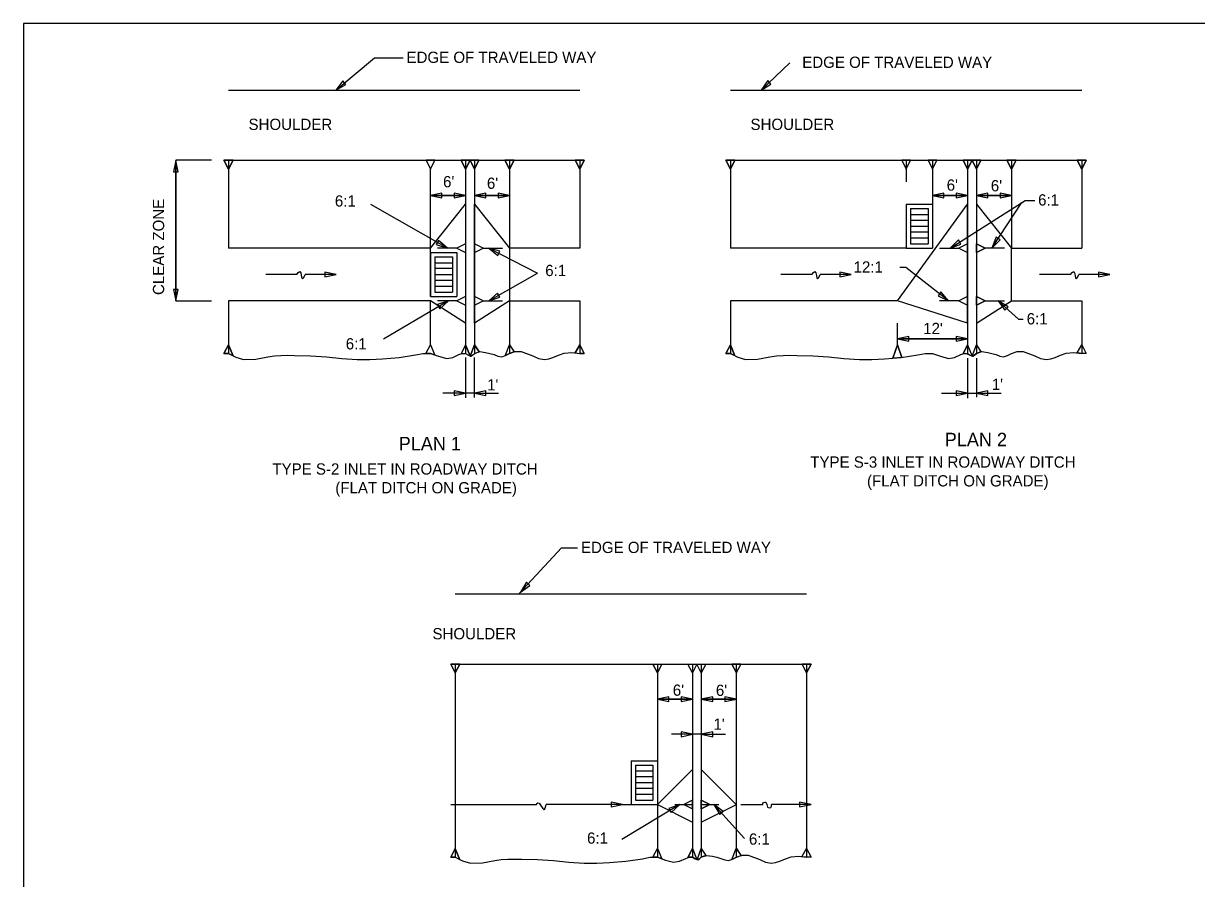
# Model space of a CAD drawing. Extents: x -439.1 to -407.9, y -458.1 to -437.7.
# Drawn here: x -439.11 to -423.48, y -449.07 to -437.68 of the extents above; entities that cross this region are included whole.
import ezdxf

# ---------------------------------------------------------------- set-up
doc = ezdxf.new("R2010")
doc.units = 0
for name, color, linetype in [('Bridge-Named Boundary', 7, 'Continuous'), ('Common-Notes', 7, 'Continuous'), ('Level 4', 7, 'Continuous'), ('Level 45', 7, 'Continuous')]:
    doc.layers.add(name, color=color, linetype=linetype)

msp = doc.modelspace()

# ---------------------------------------------------------------- linework, layer by layer
at = {"layer": 'Bridge-Named Boundary'}
msp.add_lwpolyline([(-439.109, -458.051), (-407.859, -458.051), (-407.859, -437.676), (-439.109, -437.676)], close=True, dxfattribs=at)
at = {"layer": 'Level 4'}
for p, q in [((-434.95, -438.564), (-434.433, -438.133)), ((-434.433, -438.133), (-434.053, -438.133)), ((-429.285, -438.564), (-428.902, -438.202)), ((-436.378, -438.564), (-431.699, -438.564)), ((-429.692, -438.564), (-425.013, -438.564)), ((-436.604, -439.499), (-437.081, -439.499)), ((-437.08, -441.372), (-437.08, -439.5)), ((-437.08, -439.5), (-437.08, -441.372)), ((-436.378, -439.616), (-436.439, -439.499)), ((-436.439, -439.499), (-436.378, -439.499)), ((-436.378, -439.499), (-431.699, -439.499)), ((-436.318, -439.499), (-436.378, -439.616)), ((-436.378, -439.499), (-436.378, -440.67)), ((-433.746, -439.499), (-433.687, -439.616)), ((-433.687, -439.616), (-433.63, -439.499)), ((-433.22, -439.616), (-433.28, -439.499)), ((-433.159, -439.499), (-433.22, -439.616)), ((-433.22, -439.499), (-433.22, -442.073)), ((-433.103, -439.616), (-433.159, -439.499)), ((-433.042, -439.499), (-433.103, -439.616)), ((-433.103, -439.499), (-433.103, -442.073)), ((-432.635, -439.616), (-432.696, -439.499)), ((-432.575, -439.499), (-432.635, -439.616)), ((-432.635, -439.499), (-432.635, -442.073)), ((-431.699, -439.616), (-431.76, -439.499)), ((-431.699, -439.499), (-431.639, -439.499)), ((-431.639, -439.499), (-431.699, -439.616)), ((-431.699, -439.499), (-431.699, -440.67)), ((-429.692, -439.616), (-429.753, -439.499)), ((-429.753, -439.499), (-429.692, -439.499)), ((-429.692, -439.499), (-425.013, -439.499)), ((-429.632, -439.499), (-429.692, -439.616)), ((-429.692, -439.499), (-429.692, -440.67)), ((-427.411, -439.499), (-427.352, -439.616)), ((-427.352, -439.616), (-427.294, -439.499)), ((-427.352, -439.499), (-427.352, -439.785)), ((-427.06, -439.499), (-427.001, -439.616)), ((-427.001, -439.616), (-426.944, -439.499)), ((-427.001, -439.499), (-427.001, -440.67)), ((-426.534, -439.616), (-426.594, -439.499)), ((-426.473, -439.499), (-426.534, -439.616)), ((-426.534, -439.499), (-426.534, -442.073)), ((-426.417, -439.616), (-426.473, -439.499)), ((-426.355, -439.499), (-426.417, -439.616)), ((-426.417, -439.499), (-426.417, -442.073)), ((-425.948, -439.616), (-426.01, -439.499)), ((-425.888, -439.499), (-425.948, -439.616)), ((-425.948, -439.499), (-425.948, -440.67)), ((-425.013, -439.616), (-425.074, -439.499)), ((-425.013, -439.499), (-424.953, -439.499)), ((-424.953, -439.499), (-425.013, -439.616)), ((-425.013, -439.499), (-425.013, -440.67)), ((-433.687, -440.67), (-433.687, -439.616)), ((-433.688, -439.968), (-433.22, -439.968)), ((-433.22, -439.968), (-433.688, -439.968)), ((-433.103, -439.968), (-432.635, -439.968)), ((-432.635, -439.968), (-433.103, -439.968)), ((-427.001, -439.968), (-426.534, -439.968)), ((-426.534, -439.968), (-427.001, -439.968)), ((-426.417, -439.968), (-425.949, -439.968)), ((-425.949, -439.968), (-426.417, -439.968)), ((-433.463, -440.67), (-434.48, -440.09)), ((-433.687, -440.67), (-433.22, -440.085)), ((-433.22, -440.085), (-433.22, -441.671)), ((-433.103, -441.671), (-433.103, -440.085)), ((-433.103, -440.085), (-432.635, -440.67)), ((-427.469, -441.372), (-426.534, -440.085)), ((-427.352, -440.085), (-427.001, -440.085)), ((-427.352, -440.085), (-427.352, -440.67)), ((-427.294, -440.143), (-427.06, -440.143)), ((-427.294, -440.143), (-427.294, -440.612)), ((-427.06, -440.143), (-427.06, -440.612)), ((-427.001, -440.085), (-427.001, -440.67)), ((-426.767, -440.67), (-425.766, -440.033)), ((-426.534, -441.671), (-426.534, -440.085)), ((-426.417, -440.085), (-425.948, -440.67)), ((-426.417, -440.085), (-426.417, -441.671)), ((-426.209, -440.67), (-425.811, -440.061)), ((-425.766, -440.033), (-425.64, -440.033)), ((-427.294, -440.221), (-427.06, -440.221)), ((-427.06, -440.3), (-427.294, -440.3)), ((-427.294, -440.377), (-427.06, -440.377)), ((-427.06, -440.455), (-427.294, -440.455)), ((-433.22, -440.612), (-433.337, -440.67)), ((-432.986, -440.67), (-433.103, -440.612)), ((-427.294, -440.533), (-427.06, -440.533)), ((-427.294, -440.612), (-427.06, -440.612)), ((-426.534, -440.612), (-426.651, -440.67)), ((-426.3, -440.67), (-426.417, -440.612)), ((-433.687, -440.67), (-436.378, -440.67)), ((-433.687, -441.313), (-433.687, -440.67)), ((-433.687, -440.729), (-433.687, -441.313)), ((-433.687, -440.729), (-433.337, -440.729)), ((-433.337, -440.67), (-433.594, -440.67)), ((-433.337, -440.67), (-433.22, -440.729)), ((-433.337, -440.729), (-433.337, -441.313)), ((-433.103, -440.729), (-432.986, -440.67)), ((-432.986, -440.67), (-432.729, -440.67)), ((-432.912, -440.67), (-432.26, -441.003)), ((-432.635, -440.67), (-432.635, -441.372)), ((-431.699, -440.67), (-432.635, -440.67)), ((-427.352, -440.67), (-429.692, -440.67)), ((-427.352, -440.67), (-427.001, -440.67)), ((-426.908, -440.67), (-426.651, -440.67)), ((-426.651, -440.67), (-426.534, -440.729)), ((-426.417, -440.729), (-426.3, -440.67)), ((-426.042, -440.67), (-426.3, -440.67)), ((-425.948, -441.372), (-425.948, -440.67)), ((-425.948, -440.67), (-425.013, -440.67)), ((-433.63, -440.786), (-433.396, -440.786)), ((-433.63, -440.786), (-433.63, -441.255)), ((-433.63, -440.865), (-433.396, -440.865)), ((-433.396, -440.786), (-433.396, -441.255)), ((-427.357, -440.927), (-427.435, -440.927)), ((-426.788, -441.372), (-427.357, -440.927)), ((-435.469, -441.02), (-435.88, -441.02)), ((-434.945, -441.021), (-435.357, -441.021)), ((-433.396, -440.943), (-433.63, -440.943)), ((-433.63, -441.02), (-433.396, -441.02)), ((-432.911, -441.372), (-432.26, -441.003)), ((-428.609, -441.02), (-429.021, -441.02)), ((-428.085, -441.021), (-428.497, -441.021)), ((-425.163, -441.02), (-425.574, -441.02)), ((-424.638, -441.021), (-425.05, -441.021)), ((-433.396, -441.099), (-433.63, -441.099)), ((-433.63, -441.177), (-433.396, -441.177)), ((-437.081, -441.372), (-436.604, -441.372)), ((-436.378, -441.372), (-436.378, -442.073)), ((-433.687, -441.372), (-436.378, -441.372)), ((-433.449, -441.372), (-434.315, -441.883)), ((-433.687, -441.313), (-433.337, -441.313)), ((-433.22, -441.671), (-433.687, -441.372)), ((-433.687, -441.957), (-433.687, -441.372)), ((-433.63, -441.255), (-433.396, -441.255)), ((-433.337, -441.372), (-433.594, -441.372)), ((-433.22, -441.313), (-433.337, -441.372)), ((-433.337, -441.372), (-433.22, -441.43)), ((-432.986, -441.372), (-433.103, -441.313)), ((-432.635, -441.372), (-433.103, -441.671)), ((-433.103, -441.43), (-432.986, -441.372)), ((-432.986, -441.372), (-432.729, -441.372)), ((-432.635, -441.372), (-431.699, -441.372)), ((-431.699, -441.372), (-431.699, -442.073)), ((-429.692, -441.372), (-429.692, -442.073)), ((-427.469, -441.372), (-429.692, -441.372)), ((-426.534, -441.671), (-427.469, -441.372)), ((-426.651, -441.372), (-426.908, -441.372)), ((-426.534, -441.313), (-426.651, -441.372)), ((-426.651, -441.372), (-426.534, -441.43)), ((-426.3, -441.372), (-426.417, -441.313)), ((-426.417, -441.671), (-425.948, -441.372)), ((-426.417, -441.43), (-426.3, -441.372)), ((-426.3, -441.372), (-426.042, -441.372)), ((-426.128, -441.372), (-425.854, -441.618)), ((-425.948, -441.372), (-425.013, -441.372)), ((-425.013, -441.372), (-425.013, -442.073)), ((-427.469, -441.957), (-427.469, -441.671)), ((-425.854, -441.618), (-425.792, -441.618)), ((-436.378, -441.957), (-436.439, -442.073)), ((-436.318, -442.106), (-436.378, -441.957)), ((-433.748, -442.074), (-433.687, -441.957)), ((-433.687, -441.957), (-433.628, -442.094)), ((-433.22, -441.957), (-433.281, -442.078)), ((-433.22, -441.957), (-433.161, -442.106)), ((-433.158, -442.107), (-433.103, -441.957)), ((-433.103, -441.957), (-433.041, -442.052)), ((-432.695, -442.103), (-432.635, -441.957)), ((-432.635, -441.957), (-432.575, -442.051)), ((-431.76, -442.064), (-431.699, -441.957)), ((-431.699, -441.957), (-431.639, -442.073)), ((-429.692, -441.957), (-429.753, -442.073)), ((-429.632, -442.106), (-429.692, -441.957)), ((-427.469, -441.957), (-427.528, -442.135)), ((-427.469, -441.878), (-426.534, -441.878)), ((-426.534, -441.878), (-427.469, -441.878)), ((-427.411, -442.126), (-427.469, -441.957)), ((-426.534, -441.957), (-426.594, -442.076)), ((-426.534, -441.957), (-426.473, -442.109)), ((-426.473, -442.109), (-426.417, -441.957)), ((-426.417, -441.957), (-426.356, -442.05)), ((-425.075, -442.066), (-425.013, -441.957)), ((-425.013, -441.957), (-424.953, -442.073)), ((-436.439, -442.073), (-436.378, -442.073)), ((-433.22, -442.128), (-433.22, -442.666)), ((-433.103, -442.658), (-433.103, -442.128)), ((-431.639, -442.073), (-431.699, -442.073)), ((-429.753, -442.073), (-429.692, -442.073)), ((-426.534, -442.134), (-426.534, -442.669)), ((-426.417, -442.134), (-426.417, -442.656)), ((-424.953, -442.073), (-425.013, -442.073)), ((-433.103, -442.602), (-433.521, -442.602)), ((-433.103, -442.602), (-432.781, -442.602)), ((-426.882, -442.602), (-426.086, -442.602)), ((-432.509, -445.276), (-431.944, -444.663)), ((-431.944, -444.663), (-431.73, -444.663)), ((-433.357, -445.275), (-428.678, -445.275)), ((-433.357, -446.329), (-433.417, -446.212)), ((-433.417, -446.212), (-433.357, -446.212)), ((-433.296, -446.212), (-433.357, -446.329)), ((-433.357, -446.212), (-433.357, -448.784)), ((-433.357, -446.212), (-428.678, -446.212)), ((-430.725, -446.212), (-430.666, -446.329)), ((-430.666, -446.329), (-430.608, -446.212)), ((-430.666, -446.212), (-430.666, -448.785)), ((-430.198, -446.329), (-430.259, -446.212)), ((-430.138, -446.212), (-430.198, -446.329)), ((-430.198, -446.212), (-430.198, -448.784)), ((-430.081, -446.329), (-430.138, -446.212)), ((-430.021, -446.212), (-430.081, -446.329)), ((-430.081, -446.212), (-430.081, -448.784)), ((-429.613, -446.329), (-429.674, -446.212)), ((-429.552, -446.212), (-429.614, -446.329)), ((-429.614, -446.212), (-429.614, -448.784)), ((-428.678, -446.329), (-428.738, -446.212)), ((-428.678, -446.212), (-428.617, -446.212)), ((-428.617, -446.212), (-428.678, -446.329)), ((-428.678, -446.212), (-428.678, -448.784)), ((-430.666, -446.679), (-430.198, -446.679)), ((-430.198, -446.679), (-430.666, -446.679)), ((-430.081, -446.679), (-429.613, -446.679)), ((-429.613, -446.679), (-430.081, -446.679)), ((-430.081, -447.147), (-430.476, -447.147)), ((-430.081, -447.147), (-429.758, -447.147)), ((-431.016, -447.499), (-431.016, -448.083)), ((-431.016, -447.499), (-430.666, -447.499)), ((-430.666, -447.499), (-430.666, -448.083)), ((-430.959, -447.557), (-430.725, -447.557)), ((-430.959, -447.557), (-430.959, -448.024)), ((-430.959, -447.635), (-430.725, -447.635)), ((-430.725, -447.557), (-430.725, -448.024)), ((-430.198, -447.616), (-430.666, -448.083)), ((-430.198, -447.616), (-430.198, -448.317)), ((-429.614, -448.083), (-430.081, -447.616)), ((-430.081, -447.616), (-430.081, -448.317)), ((-430.725, -447.713), (-430.959, -447.713)), ((-430.959, -447.79), (-430.725, -447.79)), ((-430.725, -447.869), (-430.959, -447.869)), ((-430.959, -447.947), (-430.725, -447.947)), ((-433.416, -448.083), (-432.275, -448.083)), ((-431.129, -448.083), (-432.148, -448.083)), ((-430.367, -448.083), (-431.141, -448.549)), ((-431.129, -448.083), (-431.016, -448.083)), ((-431.016, -448.083), (-430.666, -448.083)), ((-430.959, -448.024), (-430.725, -448.024)), ((-430.666, -448.083), (-430.198, -448.317)), ((-430.432, -448.083), (-430.198, -448.083)), ((-430.198, -448.024), (-430.315, -448.083)), ((-430.315, -448.083), (-430.198, -448.142)), ((-429.965, -448.083), (-430.081, -448.024)), ((-430.081, -448.317), (-429.613, -448.083)), ((-430.081, -448.083), (-429.848, -448.083)), ((-430.081, -448.142), (-429.965, -448.083)), ((-429.912, -448.083), (-429.503, -448.538)), ((-429.555, -448.083), (-429.262, -448.083)), ((-428.619, -448.083), (-429.145, -448.083)), ((-433.357, -448.668), (-433.417, -448.784)), ((-433.296, -448.819), (-433.357, -448.668)), ((-430.727, -448.785), (-430.666, -448.668)), ((-430.666, -448.668), (-430.607, -448.806)), ((-430.198, -448.668), (-430.259, -448.789)), ((-430.198, -448.668), (-430.14, -448.817)), ((-430.137, -448.818), (-430.081, -448.668)), ((-430.081, -448.668), (-430.019, -448.764)), ((-429.674, -448.815), (-429.614, -448.668)), ((-429.613, -448.668), (-429.551, -448.765)), ((-428.74, -448.778), (-428.678, -448.668)), ((-428.678, -448.668), (-428.617, -448.784)), ((-433.417, -448.784), (-433.357, -448.784)), ((-428.617, -448.784), (-428.683, -448.784))]:
    msp.add_line(p, q, dxfattribs=at)
for points in [[(-429.196, -438.437), (-429.285, -438.564), (-429.153, -438.483)], [(-434.854, -438.442), (-434.95, -438.564), (-434.813, -438.491)], [(-437.049, -439.652), (-437.08, -439.5), (-437.112, -439.652)], [(-436.439, -439.499), (-436.378, -439.616), (-436.318, -439.499)], [(-433.746, -439.499), (-433.687, -439.616), (-433.63, -439.499)], [(-433.28, -439.499), (-433.22, -439.616), (-433.159, -439.499)], [(-433.159, -439.499), (-433.103, -439.616), (-433.042, -439.499)], [(-432.696, -439.499), (-432.635, -439.616), (-432.575, -439.499)], [(-431.76, -439.499), (-431.699, -439.616), (-431.639, -439.499)], [(-429.753, -439.499), (-429.692, -439.616), (-429.632, -439.499)], [(-427.411, -439.499), (-427.352, -439.616), (-427.294, -439.499)], [(-427.06, -439.499), (-427.001, -439.616), (-426.944, -439.499)], [(-426.594, -439.499), (-426.534, -439.616), (-426.473, -439.499)], [(-426.473, -439.499), (-426.417, -439.616), (-426.355, -439.499)], [(-426.01, -439.499), (-425.948, -439.616), (-425.888, -439.499)], [(-425.074, -439.499), (-425.013, -439.616), (-424.953, -439.499)], [(-433.536, -439.936), (-433.688, -439.968), (-433.536, -439.999)], [(-433.372, -439.999), (-433.22, -439.968), (-433.372, -439.936)], [(-432.951, -439.936), (-433.103, -439.968), (-432.951, -439.999)], [(-432.787, -439.999), (-432.635, -439.968), (-432.787, -439.936)], [(-426.849, -439.936), (-427.001, -439.968), (-426.849, -439.999)], [(-426.686, -439.999), (-426.534, -439.968), (-426.686, -439.936)], [(-426.264, -439.936), (-426.417, -439.968), (-426.264, -439.999)], [(-426.101, -439.999), (-425.949, -439.968), (-426.101, -439.936)], [(-433.611, -440.622), (-433.463, -440.67), (-433.58, -440.567)], [(-426.656, -440.561), (-426.767, -440.67), (-426.622, -440.615)], [(-426.534, -440.612), (-426.651, -440.67), (-426.534, -440.729)], [(-426.417, -440.612), (-426.3, -440.67), (-426.417, -440.729)], [(-426.152, -440.525), (-426.209, -440.67), (-426.099, -440.56)], [(-432.763, -440.711), (-432.912, -440.67), (-432.791, -440.767)], [(-435.097, -441.052), (-434.945, -441.021), (-435.097, -440.989)], [(-428.237, -441.052), (-428.085, -441.021), (-428.237, -440.989)], [(-424.791, -441.052), (-424.638, -441.021), (-424.791, -440.989)], [(-437.112, -441.219), (-437.08, -441.372), (-437.049, -441.219)], [(-433.564, -441.477), (-433.449, -441.372), (-433.596, -441.422)], [(-432.794, -441.27), (-432.911, -441.372), (-432.763, -441.325)], [(-426.927, -441.303), (-426.788, -441.372), (-426.888, -441.253)], [(-426.534, -441.313), (-426.651, -441.372), (-426.534, -441.43)], [(-426.417, -441.313), (-426.3, -441.372), (-426.417, -441.43)], [(-425.993, -441.45), (-426.128, -441.372), (-426.036, -441.497)], [(-427.317, -441.847), (-427.469, -441.878), (-427.317, -441.91)], [(-426.686, -441.91), (-426.534, -441.878), (-426.686, -441.847)], [(-436.439, -442.073), (-436.378, -441.957), (-436.318, -442.106), (-436.378, -442.073)], [(-433.748, -442.074), (-433.687, -441.957), (-433.628, -442.094), (-433.688, -442.074)], [(-433.161, -442.106), (-433.22, -441.957), (-433.281, -442.078), (-433.265, -442.072), (-433.22, -442.074), (-433.183, -442.097)], [(-433.041, -442.052), (-433.103, -441.957), (-433.158, -442.107), (-433.15, -442.11), (-433.127, -442.096), (-433.103, -442.074)], [(-432.695, -442.103), (-432.635, -441.957), (-432.575, -442.051), (-432.635, -442.074), (-432.687, -442.1)], [(-431.639, -442.073), (-431.699, -441.957), (-431.76, -442.064), (-431.699, -442.073)], [(-429.753, -442.073), (-429.692, -441.957), (-429.632, -442.106), (-429.692, -442.074)], [(-427.53, -442.135), (-427.469, -441.957), (-427.411, -442.126)], [(-426.594, -442.076), (-426.534, -441.957), (-426.473, -442.109), (-426.556, -442.073)], [(-426.473, -442.109), (-426.417, -441.957), (-426.356, -442.05), (-426.417, -442.074), (-426.463, -442.11), (-426.48, -442.103)], [(-425.075, -442.066), (-425.013, -441.957), (-424.953, -442.073), (-425.013, -442.073)], [(-433.372, -442.633), (-433.22, -442.602), (-433.372, -442.57)], [(-432.951, -442.57), (-433.103, -442.602), (-432.951, -442.633)], [(-426.686, -442.633), (-426.534, -442.602), (-426.686, -442.57)], [(-426.264, -442.57), (-426.417, -442.602), (-426.264, -442.633)], [(-432.41, -445.122), (-432.49, -445.255), (-432.364, -445.165)], [(-433.417, -446.212), (-433.357, -446.329), (-433.296, -446.212)], [(-430.608, -446.212), (-430.666, -446.329), (-430.725, -446.212)], [(-430.138, -446.212), (-430.198, -446.329), (-430.259, -446.212)], [(-430.021, -446.212), (-430.081, -446.329), (-430.138, -446.212)], [(-429.674, -446.212), (-429.613, -446.329), (-429.552, -446.212)], [(-428.738, -446.212), (-428.678, -446.329), (-428.617, -446.212)], [(-430.514, -446.648), (-430.666, -446.679), (-430.514, -446.711)], [(-430.35, -446.711), (-430.198, -446.679), (-430.35, -446.648)], [(-429.929, -446.648), (-430.081, -446.679), (-429.929, -446.711)], [(-429.765, -446.711), (-429.613, -446.679), (-429.765, -446.648)], [(-430.35, -447.179), (-430.198, -447.147), (-430.35, -447.116)], [(-429.929, -447.116), (-430.081, -447.147), (-429.929, -447.179)], [(-431.281, -448.115), (-431.129, -448.083), (-431.281, -448.052)], [(-430.481, -448.189), (-430.367, -448.083), (-430.513, -448.135)], [(-430.198, -448.024), (-430.315, -448.083), (-430.198, -448.142)], [(-430.081, -448.024), (-429.965, -448.083), (-430.081, -448.142)], [(-429.787, -448.175), (-429.912, -448.083), (-429.834, -448.217)], [(-428.771, -448.115), (-428.619, -448.083), (-428.771, -448.052)], [(-433.417, -448.784), (-433.357, -448.668), (-433.296, -448.819), (-433.357, -448.784)], [(-430.727, -448.785), (-430.666, -448.668), (-430.607, -448.806), (-430.666, -448.785), (-430.715, -448.785)], [(-430.259, -448.789), (-430.198, -448.668), (-430.14, -448.817), (-430.161, -448.808), (-430.198, -448.785), (-430.243, -448.783)], [(-430.137, -448.818), (-430.081, -448.668), (-430.019, -448.764), (-430.081, -448.785), (-430.105, -448.808), (-430.128, -448.822)], [(-429.674, -448.815), (-429.614, -448.668), (-429.551, -448.765), (-429.613, -448.785), (-429.665, -448.812)], [(-428.74, -448.778), (-428.678, -448.668), (-428.617, -448.784), (-428.683, -448.784)]]:
    msp.add_lwpolyline(points, close=True, dxfattribs=at)
for points in [[(-435.469, -441.021), (-435.448, -440.995), (-435.427, -440.983), (-435.415, -440.999), (-435.408, -441.032), (-435.402, -441.064), (-435.394, -441.08), (-435.375, -441.059), (-435.357, -441.021)], [(-428.609, -441.021), (-428.588, -440.995), (-428.567, -440.983), (-428.555, -440.999), (-428.548, -441.032), (-428.542, -441.064), (-428.534, -441.08), (-428.515, -441.059), (-428.497, -441.021)], [(-425.163, -441.021), (-425.142, -440.995), (-425.12, -440.983), (-425.108, -440.999), (-425.101, -441.032), (-425.095, -441.064), (-425.087, -441.08), (-425.068, -441.059), (-425.05, -441.021)], [(-436.378, -442.074), (-436.281, -442.123), (-436.177, -442.153), (-436.016, -442.149), (-435.854, -442.119), (-435.766, -442.106), (-435.679, -442.098), (-435.588, -442.097), (-435.497, -442.099), (-435.284, -442.105), (-435.071, -442.116), (-434.867, -442.138), (-434.662, -442.154), (-434.494, -442.153), (-434.327, -442.143), (-434.106, -442.126), (-433.885, -442.093), (-433.786, -442.074), (-433.688, -442.074), (-433.579, -442.111), (-433.472, -442.14), (-433.392, -442.125), (-433.31, -442.089), (-433.265, -442.072), (-433.22, -442.074), (-433.183, -442.097), (-433.15, -442.11), (-433.127, -442.096), (-433.103, -442.074), (-433.031, -442.049), (-432.953, -442.059), (-432.896, -442.072), (-432.841, -442.089), (-432.79, -442.108), (-432.739, -442.116), (-432.687, -442.1), (-432.635, -442.074), (-432.558, -442.048), (-432.48, -442.046), (-432.324, -442.106), (-432.247, -442.139), (-432.169, -442.153), (-432.112, -442.144), (-432.056, -442.125), (-431.982, -442.095), (-431.907, -442.071), (-431.804, -442.061), (-431.699, -442.074)], [(-429.692, -442.074), (-429.595, -442.123), (-429.491, -442.153), (-429.33, -442.149), (-429.168, -442.119), (-429.08, -442.106), (-428.992, -442.098), (-428.901, -442.097), (-428.81, -442.099), (-428.597, -442.105), (-428.385, -442.116), (-428.18, -442.138), (-427.975, -442.154), (-427.808, -442.153), (-427.641, -442.143), (-427.42, -442.126), (-427.198, -442.093), (-427.099, -442.074), (-427.001, -442.074), (-426.893, -442.111), (-426.786, -442.14), (-426.706, -442.125), (-426.624, -442.089), (-426.578, -442.072), (-426.534, -442.074), (-426.497, -442.097), (-426.463, -442.11), (-426.44, -442.096), (-426.417, -442.074), (-426.345, -442.049), (-426.266, -442.059), (-426.209, -442.072), (-426.154, -442.089), (-426.103, -442.108), (-426.053, -442.116), (-426.001, -442.1), (-425.949, -442.074), (-425.872, -442.048), (-425.794, -442.046), (-425.638, -442.106), (-425.561, -442.139), (-425.483, -442.153), (-425.426, -442.144), (-425.369, -442.125), (-425.295, -442.095), (-425.221, -442.071), (-425.117, -442.061), (-425.013, -442.074)], [(-432.275, -448.083), (-432.268, -448.069), (-432.259, -448.059), (-432.24, -448.065), (-432.22, -448.091), (-432.193, -448.137), (-432.172, -448.154), (-432.16, -448.133), (-432.148, -448.083)], [(-429.262, -448.083), (-429.26, -448.069), (-429.252, -448.057), (-429.236, -448.05), (-429.219, -448.052), (-429.208, -448.083), (-429.197, -448.12), (-429.176, -448.127), (-429.154, -448.121), (-429.146, -448.104), (-429.145, -448.083)], [(-433.357, -448.785), (-433.259, -448.835), (-433.155, -448.864), (-432.994, -448.861), (-432.832, -448.831), (-432.745, -448.817), (-432.657, -448.81), (-432.566, -448.809), (-432.475, -448.811), (-432.262, -448.817), (-432.049, -448.828), (-431.845, -448.849), (-431.64, -448.866), (-431.472, -448.865), (-431.305, -448.855), (-431.084, -448.838), (-430.863, -448.805), (-430.764, -448.786), (-430.666, -448.785), (-430.557, -448.823), (-430.451, -448.852), (-430.371, -448.836), (-430.288, -448.801), (-430.243, -448.783), (-430.198, -448.785), (-430.161, -448.808), (-430.128, -448.822), (-430.105, -448.808), (-430.081, -448.785), (-430.009, -448.761), (-429.931, -448.77), (-429.874, -448.783), (-429.819, -448.801), (-429.768, -448.82), (-429.717, -448.828), (-429.665, -448.812), (-429.613, -448.785), (-429.536, -448.76), (-429.458, -448.758), (-429.302, -448.817), (-429.226, -448.85), (-429.148, -448.864), (-429.091, -448.856), (-429.034, -448.837), (-428.96, -448.807), (-428.885, -448.782), (-428.782, -448.773), (-428.683, -448.784)]]:
    msp.add_lwpolyline(points, dxfattribs=at)

# ---------------------------------------------------------------- texts
at = {"layer": 'Common-Notes'}
for s, p in [('PLAN 1', (-434.111, -443.364)), ('PLAN 2', (-426.838, -443.31))]:
    msp.add_text(s, height=0.18, dxfattribs=at).set_placement(p)
at = {"layer": 'Level 4'}
for s, p in [('EDGE OF TRAVELED WAY', (-434.007, -438.202)), ('EDGE OF TRAVELED WAY', (-428.736, -438.268)), ('SHOULDER', (-436.111, -439.095)), ('SHOULDER', (-429.425, -439.095)), ('TYPE S-2 INLET IN ROADWAY DITCH ', (-435.793, -443.687)), ('TYPE S-3 INLET IN ROADWAY DITCH', (-428.629, -443.595)), ('(FLAT DITCH ON GRADE)', (-427.873, -443.845)), ('(FLAT DITCH ON GRADE)', (-434.955, -443.937)), ('EDGE OF TRAVELED WAY', (-431.683, -444.732)), ('SHOULDER', (-433.661, -445.882))]:
    msp.add_text(s, height=0.15, dxfattribs=at).set_placement(p)
msp.add_text('CLEAR ZONE', height=0.15, rotation=90, dxfattribs=at).set_placement((-437.235, -441.294))
at = {"layer": 'Level 45'}
for s, p in [("6'", (-433.52, -439.859)), ("6'", (-432.936, -439.88)), ("6'", (-426.812, -439.904)), ("6'", (-426.224, -439.913)), ('6:1', (-434.961, -440.116)), ('6:1', (-425.594, -440.102)), ('6:1', (-432.159, -441.042)), ('12:1', (-428.052, -440.996)), ('6:1', (-425.746, -441.686)), ("12'", (-427.125, -441.815)), ('6:1', (-434.816, -442.019)), ("1'", (-432.934, -442.566)), ("1'", (-426.212, -442.56)), ("6'", (-430.46, -446.634)), ("6'", (-429.886, -446.636)), ("1'", (-429.919, -447.087)), ('6:1', (-431.602, -448.605)), ('6:1', (-429.446, -448.618))]:
    msp.add_text(s, height=0.15, dxfattribs=at).set_placement(p)

doc.saveas('drawing.dxf')
